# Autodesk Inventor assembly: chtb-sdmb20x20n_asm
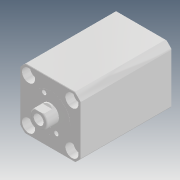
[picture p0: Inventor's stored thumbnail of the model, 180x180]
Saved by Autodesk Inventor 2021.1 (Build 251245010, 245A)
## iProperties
Company: Microsoft
Created: 2018-05
Part Number: chtb-sdmb20x20n_asm
Description: STEP AP214
Document SubType Name: Assembly
Designer: user
Title: chtb-sdmb20x20n_asm.STEP
Author: Windows
Revision Number: ÈÎºÎ
Sending System: SolidWorks 2015
Preprocessor: SwSTEP 2.0
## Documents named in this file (4)
- D:\Vault_2016\Projekty\Clamptek\Hydraulic\CHTB\CHTB-20\Inventor\CHTB-SDMB20x20N\chtb-sdmb20x20n_asm.iam
- D:\Vault_2016\Projekty\Clamptek\Hydraulic\CHTB\CHTB-20\Inventor\CHTB-SDMB20x20N\CHTB-SDMB20X20NBT.ipt
- D:\Vault_2016\Projekty\Clamptek\Hydraulic\CHTB\CHTB-20\Inventor\CHTB-SDMB20x20N\CHTB-SDMB20X20NHSG.ipt
- D:\Vault_2016\Projekty\Clamptek\Hydraulic\CHTB\CHTB-20\Inventor\CHTB-SDMB20x20N\QG_3.ipt
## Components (3 placed, 3 different names)
1. CHTB-SDMB20X20NBT_1
2. CHTB-SDMB20X20NHSG_2
3. QG_3_3
